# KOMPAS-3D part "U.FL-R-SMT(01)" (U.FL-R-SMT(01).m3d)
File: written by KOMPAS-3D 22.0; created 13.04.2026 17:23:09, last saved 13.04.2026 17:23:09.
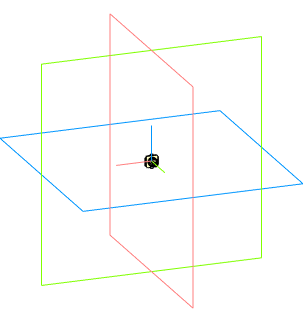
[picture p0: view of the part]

Document properties: Автор: Andrey; Полное имя файла: C:\Users\User1\Documents\U.FL-R-SMT(01).m3d

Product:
- Part/product: U.FL-R-SMT(01)

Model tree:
1. Операция без истории:1
2. Операция без истории:2
3. Операция без истории:3
4. Операция без истории:4
5. Операция без истории:5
